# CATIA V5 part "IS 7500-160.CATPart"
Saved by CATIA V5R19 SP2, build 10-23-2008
Part number: IS 7500-160
Bounding box of the stored display mesh (mm): x -74.81 to 74.81, y -74.81 to 74.81, z 0 to 475
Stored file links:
  C:\Users\Bora\Desktop\3D Katı model\IS serisi\IS 7500\IS 7500-160.CATPart
  C:\Program Files\Dassault Systemes\B19\intel_a\reffiles\standard\MetricThickPitch.txt
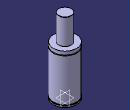
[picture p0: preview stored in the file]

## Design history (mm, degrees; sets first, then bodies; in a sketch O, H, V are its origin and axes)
Body1 (main body)
  Sketch1 on yz-plane, origin (0, 0, 0), H (0, 1, 0), V (0, 0, 1)
    point P1 (75, 290)
    point P4 (75, 285)
    point P7 (40, 474)
    point P9 (40, 474)
    point P13 (75, 290)
    point P14 (75, 285)
    line L1 (75, 290) -> (75, 312)
    line L2 (75, 15) -> (75, 285)
    line L3 (71, 15) -> (71, 8)
    arc A1 centre (39, 474) radius 1 from (40, 474) to (39, 475) ccw
    line L4 (40, 474) -> (40, 312)
    line L5 (75, 0) -> (75, 8)
    arc A2 centre (75, 287.5) radius 2.5 from (75, 290) to (75, 285) ccw
    line L6 (39, 475) -> (0, 475)
    point P15 (0, 475)
    line L7 (40, 312) -> (75, 312)
    line L8 (0, 0) -> (75, 0)
    line L9 (71, 15) -> (75, 15)
    line L10 (71, 8) -> (75, 8)
    coincidence: P15 V, P1 P13, P4 P14, P7 P9
    tangency: L6 A1
    horizontal: L7 H, L8 H, L9 H, L10 H
  Shaft1: profile Sketch1, axis Sketch1.V, angle 360
  Sketch2 on face of Shaft1 from Sketch1.L8, origin (0, 0, 0), H (1, 0, 0), V (0, -1, 0)
    point P1 (50, 0)
    distance P1 V = 50
  Hole1: placed by Sketch2, at (50, 0, 0) direction (0, 0, 1), diameter 8.376, depth 16, threaded "M10", thread diameter 10, thread depth 16, pitch 1.5
  CircPattern1: of Hole1, instances 4, angular step 90, axis from xy-plane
